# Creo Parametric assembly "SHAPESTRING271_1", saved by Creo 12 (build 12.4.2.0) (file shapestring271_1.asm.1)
Units: Custom; MM, KILOGRAM, SECS

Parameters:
  PTC_WM_ITERATION = "0"
  PTC_WM_VERSION = "-.0"
  PTC_WM_LIFECYCLE_STATE = "In Work"
  PTC_WM_LIFECYCLE = "MO_CADDocument"
  PTC_WM_CREATED_BY = "Maximilian Roepper (Z0017RMS: MO)"
  PTC_WM_CREATED_ON = "18-Sep-26 11:36:42 AM"
  PTC_WM_MODIFIED_BY = "Maximilian Roepper (Z0017RMS: MO)"
  PTC_WM_MODIFIED_ON = "18-Sep-26 11:36:46 AM"
  PDMLINKNUMBER = "PDM000071454957"
  PTC_WM_NUMBER = "PDM000071454957"

Other parameters: WEIGHT, WEIGHT_FACTOR, WEIGHT_ADD, MC_ERRORS, SUPPLIER

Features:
  1. coordinate system
  2. imported feature
  3. component "SHAPESTRING006_1"
  4. component "SHAPESTRING269_1"
  5. component "SHAPESTRING270_1"

Other named items: DRW_VIEW_ORG, ROUGH-GROB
